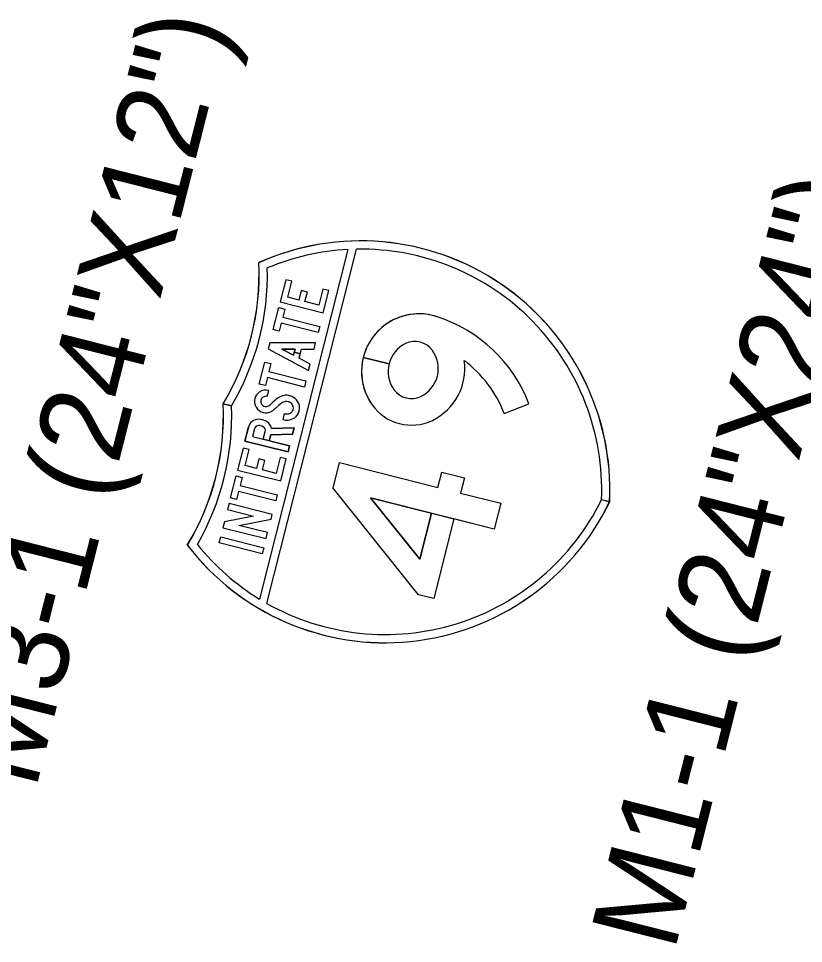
# Model space of a CAD drawing. Extents: x 670257 to 671518, y 737783 to 738188.
# Drawn here: x 670270.867 to 670273.131, y 738132.962 to 738135.629 of the extents above; entities that cross this region are included whole.
import ezdxf

# ---------------------------------------------------------------- set-up
doc = ezdxf.new("R2010")
doc.units = 0
doc.layers.add('R_SIGN_ANNOT', color=7, linetype='Continuous')
doc.layers.add('R_SIGN_HWY102', color=7, linetype='Continuous')

msp = doc.modelspace()

# ---------------------------------------------------------------- linework, layer by layer
at = {"layer": 'R_SIGN_HWY102'}
for p, q in [((670271.9354, 738134.6332), (670271.8611, 738134.652)), ((670271.8611, 738134.652), (670271.9354, 738134.6332)), ((670271.9354, 738134.6332), (670271.8611, 738134.652)), ((670271.8611, 738134.652), (670271.9354, 738134.6332)), ((670271.9354, 738134.6332), (670271.9354, 738134.6332)), ((670271.9354, 738134.6332), (670271.9354, 738134.6332)), ((670272.2675, 738134.4907), (670272.339, 738134.5185)), ((670272.2675, 738134.4907), (670272.339, 738134.5185)), ((670272.2675, 738134.4907), (670272.339, 738134.5185)), ((670271.53, 738134.4508), (670271.5198, 738134.4108)), ((670271.5474, 738134.4464), (670271.5474, 738134.4464)), ((670271.5785, 738134.4385), (670271.5785, 738134.4385)), ((670271.5785, 738134.4385), (670271.5785, 738134.4385))]:
    msp.add_line(p, q, dxfattribs=at)
for points in [[(670271.8167, 738134.9631), (670271.5616, 738133.9553)], [(670271.5831, 738133.9426), (670271.8416, 738134.964)], [(670271.5842, 738134.5394), (670271.5887, 738134.5568)], [(670271.5842, 738134.5394), (670271.5887, 738134.5568)], [(670271.5842, 738134.5394), (670271.5887, 738134.5568)], [(670271.4569, 738134.518), (670271.4811, 738134.5119)], [(670271.4811, 738134.5119), (670271.4569, 738134.518)], [(670271.6333, 738134.4899), (670271.6289, 738134.4725)], [(670271.6333, 738134.4899), (670271.6289, 738134.4725)], [(670271.6333, 738134.4899), (670271.6289, 738134.4725)], [(670271.5474, 738134.4464), (670271.5417, 738134.4238), (670271.6486, 738134.3967), (670271.6442, 738134.3793), (670271.5198, 738134.4108), (670271.53, 738134.4508)], [(670271.5474, 738134.4464), (670271.5417, 738134.4238), (670271.6486, 738134.3967), (670271.6442, 738134.3793), (670271.5198, 738134.4108), (670271.53, 738134.4508)], [(670271.5198, 738134.4108), (670271.6442, 738134.3793), (670271.6486, 738134.3967), (670271.5902, 738134.4115), (670271.5946, 738134.429), (670271.6573, 738134.4309), (670271.6618, 738134.449), (670271.5963, 738134.447)], [(670271.5474, 738134.4464), (670271.5417, 738134.4238), (670271.5728, 738134.4159), (670271.5785, 738134.4385)], [(670271.5963, 738134.447), (670271.6618, 738134.449), (670271.6573, 738134.4309), (670271.5946, 738134.429), (670271.5902, 738134.4115), (670271.5728, 738134.416), (670271.5785, 738134.4385)], [(670271.5963, 738134.447), (670271.6618, 738134.449), (670271.6573, 738134.4309), (670271.5946, 738134.429), (670271.5902, 738134.4115), (670271.5728, 738134.416), (670271.5785, 738134.4385)], [(670272.5481, 738134.2419), (670272.5719, 738134.2358)], [(670272.5719, 738134.2358), (670272.5481, 738134.2418)], [(670272.5716, 738134.2359), (670272.5719, 738134.2358)], [(670272.5719, 738134.2358), (670272.5716, 738134.2359)]]:
    msp.add_lwpolyline(points, dxfattribs=at)
for points in [[(670271.7328, 738134.8028), (670271.693, 738134.8128), (670271.6999, 738134.8401), (670271.6825, 738134.8445), (670271.6756, 738134.8172), (670271.6433, 738134.8254), (670271.6549, 738134.8714), (670271.6375, 738134.8759), (670271.6215, 738134.8124), (670271.7459, 738134.7809), (670271.7619, 738134.8444), (670271.7445, 738134.8488)], [(670271.7328, 738134.8028), (670271.693, 738134.8128), (670271.6999, 738134.8401), (670271.6825, 738134.8445), (670271.6756, 738134.8172), (670271.6433, 738134.8254), (670271.6549, 738134.8714), (670271.6375, 738134.8759), (670271.6215, 738134.8124), (670271.7459, 738134.7809), (670271.7619, 738134.8444), (670271.7445, 738134.8488)], [(670271.7328, 738134.8028), (670271.693, 738134.8128), (670271.6999, 738134.8401), (670271.6825, 738134.8445), (670271.6756, 738134.8172), (670271.6433, 738134.8254), (670271.6549, 738134.8714), (670271.6375, 738134.8759), (670271.6215, 738134.8124), (670271.7459, 738134.7809), (670271.7619, 738134.8444), (670271.7445, 738134.8488)], [(670271.6244, 738134.751), (670271.6186, 738134.7279), (670271.6012, 738134.7324), (670271.6173, 738134.7958), (670271.6347, 738134.7914), (670271.6289, 738134.7684), (670271.7358, 738134.7413), (670271.7314, 738134.7239)], [(670271.6244, 738134.751), (670271.6186, 738134.7279), (670271.6012, 738134.7324), (670271.6173, 738134.7958), (670271.6347, 738134.7914), (670271.6289, 738134.7684), (670271.7358, 738134.7413), (670271.7314, 738134.7239)], [(670271.6244, 738134.751), (670271.6186, 738134.7279), (670271.6012, 738134.7324), (670271.6173, 738134.7958), (670271.6347, 738134.7914), (670271.6289, 738134.7684), (670271.7358, 738134.7413), (670271.7314, 738134.7239)], [(670271.6761, 738134.6493), (670271.6829, 738134.6759), (670271.7192, 738134.6758), (670271.7238, 738134.6937), (670271.5915, 738134.6941), (670271.5871, 738134.6767), (670271.7036, 738134.6141), (670271.7082, 738134.6321)], [(670271.6621, 738134.667), (670271.6598, 738134.6581), (670271.6263, 738134.6761), (670271.6644, 738134.676), (670271.6621, 738134.667), (670271.6795, 738134.6626), (670271.6829, 738134.6759), (670271.7192, 738134.6758), (670271.7238, 738134.6937), (670271.5915, 738134.6941), (670271.5871, 738134.6767), (670271.7036, 738134.6141), (670271.7082, 738134.6321), (670271.6761, 738134.6493), (670271.6795, 738134.6626)], [(670271.6621, 738134.667), (670271.6598, 738134.6581), (670271.6263, 738134.6761), (670271.6644, 738134.676), (670271.6621, 738134.667), (670271.6795, 738134.6626), (670271.6829, 738134.6759), (670271.7192, 738134.6758), (670271.7238, 738134.6937), (670271.5915, 738134.6941), (670271.5871, 738134.6767), (670271.7036, 738134.6141), (670271.7082, 738134.6321), (670271.6761, 738134.6493), (670271.6795, 738134.6626)], [(670271.6644, 738134.676), (670271.6263, 738134.6761), (670271.6598, 738134.6581)], [(670271.5846, 738134.5937), (670271.5788, 738134.5707), (670271.5614, 738134.5751), (670271.5775, 738134.6385), (670271.5949, 738134.6341), (670271.5891, 738134.6111), (670271.696, 738134.584), (670271.6916, 738134.5666)], [(670271.5846, 738134.5937), (670271.5788, 738134.5707), (670271.5614, 738134.5751), (670271.5775, 738134.6385), (670271.5949, 738134.6341), (670271.5891, 738134.6111), (670271.696, 738134.584), (670271.6916, 738134.5666)], [(670271.5846, 738134.5937), (670271.5788, 738134.5707), (670271.5614, 738134.5751), (670271.5775, 738134.6385), (670271.5949, 738134.6341), (670271.5891, 738134.6111), (670271.696, 738134.584), (670271.6916, 738134.5666)], [(670271.6101, 738134.3175), (670271.5703, 738134.3276), (670271.5771, 738134.3548), (670271.5597, 738134.3592), (670271.5528, 738134.332), (670271.5205, 738134.3402), (670271.5321, 738134.3862), (670271.5147, 738134.3906), (670271.4987, 738134.3272), (670271.6231, 738134.2957), (670271.6391, 738134.3591), (670271.6217, 738134.3635)], [(670271.6101, 738134.3175), (670271.5703, 738134.3276), (670271.5771, 738134.3548), (670271.5597, 738134.3592), (670271.5528, 738134.332), (670271.5205, 738134.3402), (670271.5321, 738134.3862), (670271.5147, 738134.3906), (670271.4987, 738134.3272), (670271.6231, 738134.2957), (670271.6391, 738134.3591), (670271.6217, 738134.3635)], [(670271.6101, 738134.3175), (670271.5703, 738134.3276), (670271.5771, 738134.3548), (670271.5597, 738134.3592), (670271.5528, 738134.332), (670271.5205, 738134.3402), (670271.5321, 738134.3862), (670271.5147, 738134.3906), (670271.4987, 738134.3272), (670271.6231, 738134.2957), (670271.6391, 738134.3591), (670271.6217, 738134.3635)], [(670272.2388, 738134.1571), (670272.1227, 738134.1864), (670272.0645, 738133.9565), (670272.0204, 738133.9676), (670271.7743, 738134.2746), (670271.7931, 738134.349), (670272.0765, 738134.2772), (670272.0876, 738134.3214), (670272.1527, 738134.3049), (670272.1415, 738134.2608), (670272.2577, 738134.2314)], [(670272.0876, 738134.3214), (670272.1527, 738134.3049), (670272.1415, 738134.2608), (670272.2577, 738134.2314), (670272.2388, 738134.1571), (670271.8821, 738134.2473), (670272.0241, 738134.0703), (670272.0577, 738134.2029), (670272.1227, 738134.1864), (670272.0645, 738133.9565), (670272.0204, 738133.9676), (670271.7743, 738134.2746), (670271.7931, 738134.349), (670272.0765, 738134.2772)], [(670272.0876, 738134.3214), (670272.1527, 738134.3049), (670272.1415, 738134.2608), (670272.2577, 738134.2314), (670272.2388, 738134.1571), (670271.8821, 738134.2473), (670272.0241, 738134.0703), (670272.0577, 738134.2029), (670272.1227, 738134.1864), (670272.0645, 738133.9565), (670272.0204, 738133.9676), (670271.7743, 738134.2746), (670271.7931, 738134.349), (670272.0765, 738134.2772)], [(670271.5017, 738134.2657), (670271.4958, 738134.2427), (670271.4784, 738134.2471), (670271.4945, 738134.3105), (670271.5119, 738134.3061), (670271.5061, 738134.2831), (670271.613, 738134.2561), (670271.6086, 738134.2386)], [(670271.5017, 738134.2657), (670271.4958, 738134.2427), (670271.4784, 738134.2471), (670271.4945, 738134.3105), (670271.5119, 738134.3061), (670271.5061, 738134.2831), (670271.613, 738134.2561), (670271.6086, 738134.2386)], [(670271.5017, 738134.2657), (670271.4958, 738134.2427), (670271.4784, 738134.2471), (670271.4945, 738134.3105), (670271.5119, 738134.3061), (670271.5061, 738134.2831), (670271.613, 738134.2561), (670271.6086, 738134.2386)], [(670271.5951, 738134.1853), (670271.5986, 738134.199), (670271.4742, 738134.2305), (670271.4698, 738134.2131), (670271.545, 738134.194), (670271.4609, 738134.178), (670271.4566, 738134.1608), (670271.581, 738134.1294), (670271.5854, 738134.1468), (670271.5027, 738134.1677)], [(670271.5951, 738134.1853), (670271.5986, 738134.199), (670271.4742, 738134.2305), (670271.4698, 738134.2131), (670271.545, 738134.194), (670271.4609, 738134.178), (670271.4566, 738134.1608), (670271.581, 738134.1294), (670271.5854, 738134.1468), (670271.5027, 738134.1677)], [(670271.5951, 738134.1853), (670271.5986, 738134.199), (670271.4742, 738134.2305), (670271.4698, 738134.2131), (670271.545, 738134.194), (670271.4609, 738134.178), (670271.4566, 738134.1608), (670271.581, 738134.1294), (670271.5854, 738134.1468), (670271.5027, 738134.1677)], [(670272.0241, 738134.0703), (670271.8821, 738134.2473), (670272.0577, 738134.2029)], [(670271.4456, 738134.1173), (670271.45, 738134.1347), (670271.5743, 738134.1032), (670271.5699, 738134.0858)], [(670271.4456, 738134.1173), (670271.45, 738134.1347), (670271.5743, 738134.1032), (670271.5699, 738134.0858)], [(670271.4456, 738134.1173), (670271.45, 738134.1347), (670271.5743, 738134.1032), (670271.5699, 738134.0858)]]:
    msp.add_lwpolyline(points, close=True, dxfattribs=at)
for centre, radius, start, end in [((670271.8538, 738134.2692), 0.7188, 357.337, 114.1302), ((670271.8538, 738134.2692), 0.7188, 357.337, 114.1302), ((670271.8538, 738134.2692), 0.7186, 357.3411, 114.1164), ((670271.8538, 738134.2692), 0.6949, 93.0624, 112.8033), ((670271.8538, 738134.2692), 0.6949, 357.7406, 91.0045), ((670270.8419, 738134.8903), 0.7188, 328.8092, 2.79), ((670270.8419, 738134.8903), 0.7188, 328.8082, 2.79), ((670270.8419, 738134.8903), 0.7191, 328.8143, 2.7762), ((670270.8419, 738134.8903), 0.7428, 329.3731, 1.5066), ((670270.7389, 738134.483), 0.7188, 328.8082, 2.79), ((670270.7389, 738134.483), 0.7188, 328.8082, 2.79), ((670270.7389, 738134.483), 0.7191, 328.8219, 2.7838), ((670270.7389, 738134.483), 0.7428, 330.0915, 2.226), ((670271.9243, 738134.548), 0.7188, 217.4679, 334.2621), ((670271.9243, 738134.548), 0.7188, 217.4679, 334.2621), ((670271.9243, 738134.548), 0.7186, 217.4817, 334.258), ((670271.9243, 738134.548), 0.6949, 240.5936, 333.8585), ((670271.9243, 738134.548), 0.6949, 218.7948, 238.5357)]:
    msp.add_arc(centre, radius, start, end, dxfattribs=at)
for centre, major_axis, ratio, start_param, end_param in [((670272.0223, 738134.6114), (-0.1611, 0.0408), 0.999994, 4.64468, 7.149545), ((670272.0223, 738134.6114), (-0.1611, 0.0408), 0.999994, 4.64468, 6.284272), ((670272.0223, 738134.6114), (-0.1611, 0.0408), 0.999994, 4.64468, 6.284272), ((670271.9415, 738134.3639), (-0.4135, 0.1046), 0.999994, 3.760338, 4.64468), ((670271.9415, 738134.3639), (-0.4135, 0.1046), 0.999994, 3.760338, 4.64468), ((670271.9415, 738134.3639), (-0.4135, 0.1046), 0.999994, 3.760338, 4.64468), ((670272.0102, 738134.6355), (-0.0604, 0.0153), 0.999994, 4.014643, 5.410135), ((670272.0102, 738134.6355), (-0.0604, 0.0153), 0.999994, 4.014643, 5.410135), ((670272.0102, 738134.6355), (-0.0604, 0.0153), 0.999994, 4.014643, 5.410135), ((670272.0218, 738134.6113), (-0.0864, 0.0219), 0.999994, 5.410135, 7.156235), ((670272.0218, 738134.6113), (-0.0864, 0.0219), 0.999994, 5.410135, 6.283185), ((670272.0218, 738134.6113), (-0.0864, 0.0219), 0.999994, 5.410135, 6.283185), ((670272.0223, 738134.6114), (-0.1611, 0.0408), 0.999994, 0.001231, 0.86636), ((670272.0223, 738134.6114), (-0.1611, 0.0408), 0.999994, 0.001231, 0.86636), ((670271.9884, 738134.6198), (-0.0864, 0.0219), 0.999994, 2.268543, 4.014643), ((670271.9884, 738134.6198), (-0.0864, 0.0219), 0.999994, 2.268543, 4.014643), ((670271.9884, 738134.6198), (-0.0864, 0.0219), 0.999994, 2.268543, 4.014643), ((670272.0218, 738134.6113), (-0.0864, 0.0219), 0.999994, 0.000269, 0.87305), ((670272.0218, 738134.6113), (-0.0864, 0.0219), 0.999994, 0.000269, 0.87305), ((670271.9884, 738134.6198), (-0.1607, 0.0407), 0.999994, 2.268543, 3.529077), ((670271.9884, 738134.6198), (-0.1607, 0.0407), 0.999994, 2.268543, 3.529077), ((670271.9884, 738134.6198), (-0.1607, 0.0407), 0.999994, 2.268543, 3.529077), ((670271.9415, 738134.3639), (-0.3391, 0.0858), 0.999994, 3.760338, 4.312274), ((670271.9415, 738134.3639), (-0.3391, 0.0858), 0.999994, 3.760338, 4.312274), ((670271.9415, 738134.3639), (-0.3391, 0.0858), 0.999994, 3.760338, 4.312274), ((670271.5795, 738134.5256), (-0.031, 0.0078), 0.999999, 5.561989, 6.283185), ((670271.5795, 738134.5256), (-0.031, 0.0078), 0.999999, 5.561989, 6.283185), ((670271.5795, 738134.5256), (-0.031, 0.0078), 0.999999, 5.561989, 6.283185), ((670271.5804, 738134.5243), (-0.0325, 0.0082), 0.999999, 4.712389, 5.561989), ((670271.5804, 738134.5243), (-0.0325, 0.0082), 0.999999, 4.712389, 5.561989), ((670271.5804, 738134.5243), (-0.0325, 0.0082), 0.999999, 4.712389, 5.561989), ((670271.6391, 738134.5037), (-0.0379, 0.0096), 0.999999, 4.712389, 5.373599), ((670271.6391, 738134.5037), (-0.0379, 0.0096), 0.999999, 4.712389, 5.373599), ((670271.6391, 738134.5037), (-0.0379, 0.0096), 0.999999, 4.712389, 5.373599), ((670272.0001, 738134.5956), (-0.0604, 0.0153), 0.999994, 0.87305, 2.268543), ((670272.0001, 738134.5956), (-0.0604, 0.0153), 0.999994, 0.87305, 2.268543), ((670272.0001, 738134.5956), (-0.0604, 0.0153), 0.999994, 0.87305, 2.268543), ((670271.5806, 738134.5253), (-0.032, 0.0081), 0.999999, 6.283184, 7.853982), ((670271.5806, 738134.5253), (-0.032, 0.0081), 0.999999, 6.283184, 7.853982), ((670271.5806, 738134.5253), (-0.032, 0.0081), 0.999999, 6.283184, 7.853982), ((670271.5806, 738134.5253), (-0.0146, 0.0037), 0.999999, 6.283183, 7.853981), ((670271.5806, 738134.5253), (-0.0146, 0.0037), 0.999999, 6.283183, 7.853981), ((670271.5806, 738134.5253), (-0.0146, 0.0037), 0.999999, 6.283183, 7.853981), ((670271.5795, 738134.5256), (-0.0135, 0.0034), 0.999999, 5.561989, 6.283185), ((670271.5795, 738134.5256), (-0.0135, 0.0034), 0.999999, 5.561989, 6.283185), ((670271.5795, 738134.5256), (-0.0135, 0.0034), 0.999999, 5.561989, 6.283185), ((670271.5804, 738134.5243), (-0.0151, 0.0038), 0.999999, 4.712389, 5.561989), ((670271.5804, 738134.5243), (-0.0151, 0.0038), 0.999999, 4.712389, 5.561989), ((670271.5804, 738134.5243), (-0.0151, 0.0038), 0.999999, 4.712389, 5.561989), ((670272.1065, 738133.9622), (-0.732, 0.1852), 0.999999, 5.679143, 5.709053), ((670272.1065, 738133.9622), (-0.732, 0.1852), 0.999999, 5.679143, 5.709053), ((670272.1065, 738133.9622), (-0.732, 0.1852), 0.999999, 5.679143, 5.709053), ((670272.1065, 738133.9622), (-0.7146, 0.1808), 0.999999, 5.679143, 5.709053), ((670272.1065, 738133.9622), (-0.7146, 0.1808), 0.999999, 5.679143, 5.709053), ((670272.1065, 738133.9622), (-0.7146, 0.1808), 0.999999, 5.679143, 5.709053), ((670271.6456, 738134.4889), (-0.0536, 0.0136), 0.999999, 5.373599, 5.679143), ((670271.6456, 738134.4889), (-0.0536, 0.0136), 0.999999, 5.373599, 5.679143), ((670271.6456, 738134.4889), (-0.0536, 0.0136), 0.999999, 5.373599, 5.679143), ((670271.6456, 738134.4889), (-0.0361, 0.0091), 0.999999, 5.373599, 5.679143), ((670271.6456, 738134.4889), (-0.0361, 0.0091), 0.999999, 5.373599, 5.679143), ((670271.6456, 738134.4889), (-0.0361, 0.0091), 0.999999, 5.373599, 5.679143), ((670271.6391, 738134.5037), (-0.0205, 0.0052), 0.999999, 4.712389, 5.373599), ((670271.6391, 738134.5037), (-0.0205, 0.0052), 0.999999, 4.712389, 5.373599), ((670271.6391, 738134.5037), (-0.0205, 0.0052), 0.999999, 4.712389, 5.373599), ((670271.6382, 738134.5002), (-0.024, 0.0061), 0.999999, 4.552917, 4.712389), ((670271.6382, 738134.5002), (-0.024, 0.0061), 0.999999, 4.552917, 4.712389), ((670271.6382, 738134.5002), (-0.024, 0.0061), 0.999999, 4.552917, 4.712389), ((670271.64, 738134.5044), (-0.0195, 0.0049), 0.999999, 3.967076, 4.552917), ((670271.64, 738134.5044), (-0.0195, 0.0049), 0.999999, 3.967076, 4.552917), ((670271.64, 738134.5044), (-0.0195, 0.0049), 0.999999, 3.967076, 4.552917), ((670271.6382, 738134.5002), (-0.0414, 0.0105), 0.999999, 4.552917, 4.712389), ((670271.6382, 738134.5002), (-0.0414, 0.0105), 0.999999, 4.552917, 4.712389), ((670271.6382, 738134.5002), (-0.0414, 0.0105), 0.999999, 4.552917, 4.712389), ((670271.64, 738134.5044), (-0.0369, 0.0093), 0.999999, 3.967076, 4.552917), ((670271.64, 738134.5044), (-0.0369, 0.0093), 0.999999, 3.967076, 4.552917), ((670271.64, 738134.5044), (-0.0369, 0.0093), 0.999999, 3.967076, 4.552917), ((670271.6429, 738134.5063), (-0.0336, 0.0085), 0.999999, 3.141593, 3.967076), ((670271.6429, 738134.5063), (-0.0336, 0.0085), 0.999999, 3.141593, 3.967076), ((670271.6429, 738134.5063), (-0.0336, 0.0085), 0.999999, 3.141593, 3.967076), ((670271.5806, 738134.5254), (-0.0321, 0.0081), 0.999999, 1.570796, 2.321595), ((670271.5806, 738134.5254), (-0.0321, 0.0081), 0.999999, 1.570796, 2.321595), ((670271.5806, 738134.5254), (-0.0321, 0.0081), 0.999999, 1.570796, 2.321595), ((670271.5806, 738134.5254), (-0.0147, 0.0037), 0.999999, 1.570796, 2.321595), ((670271.5806, 738134.5254), (-0.0147, 0.0037), 0.999999, 1.570796, 2.321595), ((670271.5806, 738134.5254), (-0.0147, 0.0037), 0.999999, 1.570796, 2.321595), ((670271.577, 738134.5319), (-0.0219, 0.0055), 0.999999, 2.321595, 2.56746), ((670271.577, 738134.5319), (-0.0219, 0.0055), 0.999999, 2.321595, 2.56746), ((670271.577, 738134.5319), (-0.0219, 0.0055), 0.999999, 2.321595, 2.56746), ((670271.577, 738134.5319), (-0.0393, 0.01), 0.999999, 2.321595, 2.56746), ((670271.577, 738134.5319), (-0.0393, 0.01), 0.999999, 2.321595, 2.56746), ((670271.577, 738134.5319), (-0.0393, 0.01), 0.999999, 2.321595, 2.56746), ((670271.6412, 738134.5098), (-0.0201, 0.0051), 0.999999, 1.909925, 2.431476), ((670271.6412, 738134.5098), (-0.0201, 0.0051), 0.999999, 1.909925, 2.431476), ((670271.6412, 738134.5098), (-0.0201, 0.0051), 0.999999, 1.909925, 2.431476), ((670271.6459, 738134.5032), (-0.0123, 0.0031), 0.999999, 2.431476, 2.811358), ((670271.6459, 738134.5032), (-0.0123, 0.0031), 0.999999, 2.431476, 2.811358), ((670271.6459, 738134.5032), (-0.0123, 0.0031), 0.999999, 2.431476, 2.811358), ((670271.6401, 738134.507), (-0.019, 0.0048), 0.999999, 2.811358, 3.141593), ((670271.6401, 738134.507), (-0.019, 0.0048), 0.999999, 2.811358, 3.141593), ((670271.6401, 738134.507), (-0.019, 0.0048), 0.999999, 2.811358, 3.141593), ((670271.6429, 738134.5063), (-0.0162, 0.0041), 0.999999, 3.141593, 3.967076), ((670271.6429, 738134.5063), (-0.0162, 0.0041), 0.999999, 3.141593, 3.967076), ((670271.6429, 738134.5063), (-0.0162, 0.0041), 0.999999, 3.141593, 3.967076), ((670271.6401, 738134.507), (-0.0364, 0.0092), 0.999999, 2.811358, 3.141593), ((670271.6401, 738134.507), (-0.0364, 0.0092), 0.999999, 2.811358, 3.141593), ((670271.6401, 738134.507), (-0.0364, 0.0092), 0.999999, 2.811358, 3.141593), ((670272.0001, 738134.5956), (-0.1347, 0.0341), 0.999994, 0.86636, 2.268543), ((670272.0001, 738134.5956), (-0.1347, 0.0341), 0.999994, 0.86636, 2.268543), ((670272.0001, 738134.5956), (-0.1347, 0.0341), 0.999994, 0.86636, 2.268543), ((670271.5592, 738134.4434), (-0.0292, 0.0074), 0.999996, 4.954755, 6.283185), ((670271.5592, 738134.4434), (-0.0292, 0.0074), 0.999996, 4.954755, 6.283185), ((670271.5592, 738134.4434), (-0.0292, 0.0074), 0.999996, 4.954755, 6.283185), ((670271.5591, 738134.4273), (-0.0448, 0.0113), 0.999996, 4.470023, 4.954755), ((670271.5591, 738134.4273), (-0.0448, 0.0113), 0.999996, 4.470023, 4.954755), ((670271.5591, 738134.4273), (-0.0448, 0.0113), 0.999996, 4.470023, 4.954755), ((670271.5667, 738134.4415), (-0.0292, 0.0074), 0.999996, 3.574819, 4.470023), ((670271.5667, 738134.4415), (-0.0292, 0.0074), 0.999996, 3.574819, 4.470023), ((670271.5667, 738134.4415), (-0.0292, 0.0074), 0.999996, 3.574819, 4.470023), ((670271.6405, 738134.5184), (-0.0459, 0.0116), 0.999999, 1.570808, 1.909921), ((670271.6405, 738134.5184), (-0.0459, 0.0116), 0.999999, 1.570808, 1.909921), ((670271.6405, 738134.5184), (-0.0459, 0.0116), 0.999999, 1.570808, 1.909921), ((670271.6405, 738134.5184), (-0.0285, 0.0072), 0.999999, 1.570816, 1.909918), ((670271.6405, 738134.5184), (-0.0285, 0.0072), 0.999999, 1.570816, 1.909918), ((670271.6405, 738134.5184), (-0.0285, 0.0072), 0.999999, 1.570816, 1.909918), ((670271.6412, 738134.5098), (-0.0375, 0.0095), 0.999999, 1.909925, 2.431476), ((670271.6412, 738134.5098), (-0.0375, 0.0095), 0.999999, 1.909925, 2.431476), ((670271.6412, 738134.5098), (-0.0375, 0.0095), 0.999999, 1.909925, 2.431476), ((670271.6459, 738134.5032), (-0.0297, 0.0075), 0.999999, 2.431476, 2.811358), ((670271.6459, 738134.5032), (-0.0297, 0.0075), 0.999999, 2.431476, 2.811358), ((670271.6459, 738134.5032), (-0.0297, 0.0075), 0.999999, 2.431476, 2.811358), ((670271.5592, 738134.4434), (-0.0118, 0.003), 0.999996, 4.954755, 6.283185), ((670271.5592, 738134.4434), (-0.0118, 0.003), 0.999996, 4.954755, 6.283185), ((670271.5592, 738134.4434), (-0.0118, 0.003), 0.999996, 4.954755, 6.283185), ((670271.5591, 738134.4273), (-0.0274, 0.0069), 0.999996, 4.470023, 4.954755), ((670271.5591, 738134.4273), (-0.0274, 0.0069), 0.999996, 4.470023, 4.954755), ((670271.5591, 738134.4273), (-0.0274, 0.0069), 0.999996, 4.470023, 4.954755), ((670271.5667, 738134.4415), (-0.0118, 0.003), 0.999996, 3.141593, 4.470023), ((670271.5667, 738134.4415), (-0.0118, 0.003), 0.999996, 3.141593, 4.470023), ((670271.5667, 738134.4415), (-0.0118, 0.003), 0.999996, 3.141593, 4.470023)]:
    msp.add_ellipse(centre, major_axis=major_axis, ratio=ratio, start_param=start_param, end_param=end_param, dxfattribs=at)

# ---------------------------------------------------------------- texts
at = {"layer": 'R_SIGN_ANNOT'}
for s, p in [('M3-1 (24"X12")', (670270.916, 738133.4022)), ('M1-1 (24"X24")', (670272.7579, 738132.9356))]:
    msp.add_text(s, height=0.25, rotation=75.7686, dxfattribs=at).set_placement(p)

doc.saveas('drawing.dxf')
